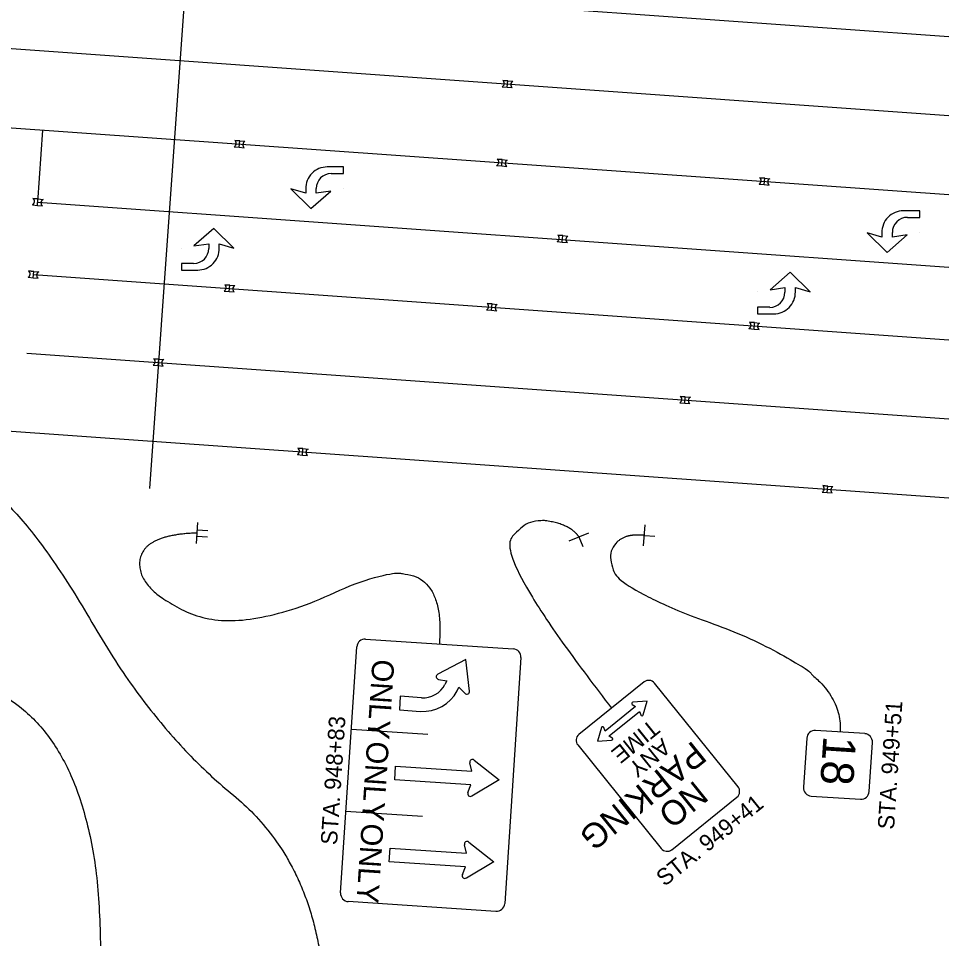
# Model space of a CAD drawing. Extents: x 1847379 to 1850904, y 217032 to 220169.
# Drawn here: x 1848989.3 to 1849129.7, y 218737.1 to 218877.1 of the extents above; entities that cross this region are included whole.
import ezdxf

# ---------------------------------------------------------------- set-up
doc = ezdxf.new("R2010")
doc.units = 0
for name, color, linetype in [('BR_P_Gen_Phase_Construction', 7, 'Continuous'), ('PM_P_Cells', 7, 'Continuous'), ('PM_P_Channelizing_Line', 7, 'Continuous'), ('PM_P_CL_Double_Solid', 7, 'Continuous'), ('PM_P_Edge_Line', 7, 'Continuous'), ('PM_P_Lane_Line', 7, 'Continuous'), ('PM_P_Stop_Line', 7, 'Continuous'), ('PM_X_Cells', 7, 'Continuous'), ('SN_X_Public', 7, 'Continuous')]:
    doc.layers.add(name, color=color, linetype=linetype)

msp = doc.modelspace()

# ---------------------------------------------------------------- linework, layer by layer
at = {"layer": 'BR_P_Gen_Phase_Construction'}
msp.add_line((1849015.28, 218890.32), (1849009.23, 218805.57), dxfattribs=at)
at = {"layer": 'PM_P_Cells'}
for p, q in [((1849062.86, 218866.66), (1849063.63, 218866.6)), ((1849062.86, 218866.66), (1849063.63, 218866.6)), ((1849063.72, 218867.57), (1849062.95, 218867.64)), ((1849062.95, 218867.64), (1849063.72, 218867.57)), ((1849063.63, 218866.6), (1849063.72, 218867.57)), ((1849063.63, 218866.6), (1849064.4, 218866.53)), ((1849063.72, 218867.57), (1849064.49, 218867.5)), ((1849022.98, 218858.44), (1849022.22, 218858.51)), ((1849022.22, 218858.51), (1849022.98, 218858.44)), ((1849022.9, 218857.47), (1849022.98, 218858.44)), ((1849022.98, 218858.44), (1849023.75, 218858.38)), ((1849022.13, 218857.54), (1849022.9, 218857.47)), ((1849022.13, 218857.54), (1849022.9, 218857.47)), ((1849022.9, 218857.47), (1849023.66, 218857.4)), ((1849062.88, 218855.6), (1849062.12, 218855.67)), ((1849062.12, 218855.67), (1849062.88, 218855.6)), ((1849062.8, 218854.62), (1849062.88, 218855.6)), ((1849062.88, 218855.6), (1849063.65, 218855.53)), ((1849038.76, 218854.48), (1849036.28, 218854.48)), ((1849038.76, 218853.48), (1849038.76, 218854.48)), ((1849062.03, 218854.69), (1849062.8, 218854.62)), ((1849062.03, 218854.69), (1849062.8, 218854.62)), ((1849062.8, 218854.62), (1849063.56, 218854.56)), ((1849036.89, 218853.48), (1849038.76, 218853.48)), ((1849102.78, 218852.75), (1849102.01, 218852.82)), ((1849102.01, 218852.82), (1849102.78, 218852.75)), ((1849102.69, 218851.78), (1849102.78, 218852.75)), ((1849102.78, 218852.75), (1849103.55, 218852.68)), ((1849030.76, 218851.15), (1849030.76, 218851.15)), ((1849033, 218850.48), (1849030.76, 218851.15)), ((1849030.76, 218851.15), (1849033.8, 218848.15)), ((1849033, 218851.15), (1849033, 218850.48)), ((1849034.6, 218850.48), (1849034.6, 218851.18)), ((1849038.76, 218851.15), (1849038.76, 218851.15)), ((1849101.93, 218851.85), (1849102.69, 218851.78)), ((1849101.93, 218851.85), (1849102.69, 218851.78)), ((1849102.69, 218851.78), (1849103.46, 218851.71)), ((1848992.29, 218849.61), (1848991.53, 218849.68)), ((1848991.53, 218849.68), (1848992.29, 218849.61)), ((1849033.8, 218848.15), (1849036.84, 218850.81)), ((1849036.84, 218850.81), (1849034.6, 218850.48)), ((1848991.44, 218848.7), (1848992.21, 218848.63)), ((1848991.44, 218848.7), (1848992.21, 218848.63)), ((1848992.21, 218848.63), (1848992.29, 218849.61)), ((1848992.21, 218848.63), (1848992.97, 218848.57)), ((1848992.29, 218849.61), (1848993.06, 218849.54)), ((1849126.35, 218847.81), (1849123.87, 218847.81)), ((1849126.35, 218846.81), (1849126.35, 218847.81)), ((1849124.49, 218846.81), (1849126.35, 218846.81)), ((1849019.05, 218845.13), (1849016.01, 218842.46)), ((1849022.09, 218842.13), (1849019.05, 218845.13)), ((1849072.1, 218844.03), (1849071.33, 218844.1)), ((1849071.33, 218844.1), (1849072.1, 218844.03)), ((1849118.35, 218844.48), (1849118.35, 218844.48)), ((1849120.59, 218843.81), (1849118.35, 218844.48)), ((1849118.35, 218844.48), (1849121.39, 218841.48)), ((1849120.59, 218844.48), (1849120.59, 218843.81)), ((1849121.39, 218841.48), (1849124.43, 218844.14)), ((1849122.19, 218843.81), (1849122.19, 218844.51)), ((1849124.43, 218844.14), (1849122.19, 218843.81)), ((1849126.35, 218844.48), (1849126.35, 218844.48)), ((1849016.01, 218842.46), (1849018.25, 218842.79)), ((1849018.25, 218842.79), (1849018.25, 218842.09)), ((1849019.85, 218842.13), (1849019.85, 218842.79)), ((1849019.85, 218842.79), (1849022.09, 218842.13)), ((1849071.24, 218843.12), (1849072.01, 218843.05)), ((1849071.24, 218843.12), (1849072.01, 218843.05)), ((1849072.01, 218843.05), (1849072.1, 218844.03)), ((1849072.01, 218843.05), (1849072.78, 218842.99)), ((1849072.1, 218844.03), (1849072.87, 218843.96)), ((1849014.09, 218842.13), (1849014.09, 218842.13)), ((1849022.09, 218842.13), (1849022.09, 218842.13)), ((1848991.64, 218838.6), (1848990.87, 218838.67)), ((1848990.87, 218838.67), (1848991.64, 218838.6)), ((1848991.55, 218837.63), (1848991.64, 218838.6)), ((1848991.64, 218838.6), (1848992.4, 218838.53)), ((1849015.96, 218839.79), (1849014.09, 218839.79)), ((1849014.09, 218839.79), (1849014.09, 218838.79)), ((1849014.09, 218838.79), (1849016.57, 218838.79)), ((1849106.65, 218838.46), (1849103.61, 218835.79)), ((1849109.69, 218835.46), (1849106.65, 218838.46)), ((1848990.78, 218837.7), (1848991.55, 218837.63)), ((1848990.78, 218837.7), (1848991.55, 218837.63)), ((1848991.55, 218837.63), (1848992.32, 218837.56)), ((1849021.45, 218836.5), (1849020.68, 218836.57)), ((1849020.68, 218836.57), (1849021.45, 218836.5)), ((1849021.36, 218835.53), (1849021.45, 218836.5)), ((1849021.45, 218836.5), (1849022.22, 218836.43)), ((1849103.61, 218835.79), (1849105.85, 218836.13)), ((1849105.85, 218836.13), (1849105.85, 218835.42)), ((1849107.45, 218835.46), (1849107.45, 218836.13)), ((1849107.45, 218836.13), (1849109.69, 218835.46)), ((1849020.59, 218835.6), (1849021.36, 218835.53)), ((1849020.59, 218835.6), (1849021.36, 218835.53)), ((1849021.36, 218835.53), (1849022.13, 218835.46)), ((1849101.69, 218835.46), (1849101.69, 218835.46)), ((1849109.69, 218835.46), (1849109.69, 218835.46)), ((1849061.35, 218833.65), (1849060.58, 218833.72)), ((1849060.58, 218833.72), (1849061.35, 218833.65)), ((1849061.26, 218832.68), (1849061.35, 218833.65)), ((1849061.35, 218833.65), (1849062.12, 218833.58)), ((1849103.55, 218833.13), (1849101.69, 218833.13)), ((1849101.69, 218833.13), (1849101.69, 218832.13)), ((1849060.49, 218832.75), (1849061.26, 218832.68)), ((1849060.49, 218832.75), (1849061.26, 218832.68)), ((1849061.26, 218832.68), (1849062.03, 218832.61)), ((1849101.69, 218832.13), (1849104.17, 218832.13)), ((1849101.25, 218830.8), (1849100.48, 218830.87)), ((1849100.48, 218830.87), (1849101.25, 218830.8)), ((1849101.16, 218829.83), (1849101.25, 218830.8)), ((1849101.25, 218830.8), (1849102.01, 218830.73)), ((1849100.39, 218829.9), (1849101.16, 218829.83)), ((1849100.39, 218829.9), (1849101.16, 218829.83)), ((1849101.16, 218829.83), (1849101.93, 218829.76)), ((1849010.65, 218825.24), (1849009.88, 218825.31)), ((1849009.88, 218825.31), (1849010.65, 218825.24)), ((1849010.56, 218824.27), (1849010.65, 218825.24)), ((1849010.65, 218825.24), (1849011.41, 218825.17)), ((1849009.79, 218824.34), (1849010.56, 218824.27)), ((1849009.79, 218824.34), (1849010.56, 218824.27)), ((1849010.56, 218824.27), (1849011.33, 218824.2)), ((1849090.71, 218819.52), (1849089.95, 218819.59)), ((1849089.95, 218819.59), (1849090.71, 218819.52)), ((1849090.63, 218818.55), (1849090.71, 218819.52)), ((1849090.71, 218819.52), (1849091.48, 218819.46)), ((1849089.86, 218818.62), (1849090.63, 218818.55)), ((1849089.86, 218818.62), (1849090.63, 218818.55)), ((1849090.63, 218818.55), (1849091.39, 218818.48)), ((1849031.73, 218810.74), (1849032.5, 218810.67)), ((1849031.73, 218810.74), (1849032.5, 218810.67)), ((1849032.58, 218811.64), (1849031.82, 218811.71)), ((1849031.82, 218811.71), (1849032.58, 218811.64)), ((1849032.5, 218810.67), (1849032.58, 218811.64)), ((1849032.5, 218810.67), (1849033.26, 218810.6)), ((1849032.58, 218811.64), (1849033.35, 218811.57)), ((1849111.52, 218805.04), (1849112.29, 218804.97)), ((1849111.52, 218805.04), (1849112.29, 218804.97)), ((1849112.38, 218805.95), (1849111.61, 218806.02)), ((1849111.61, 218806.02), (1849112.38, 218805.95)), ((1849112.29, 218804.97), (1849112.38, 218805.95)), ((1849112.29, 218804.97), (1849113.06, 218804.91)), ((1849112.38, 218805.95), (1849113.15, 218805.88))]:
    msp.add_line(p, q, dxfattribs=at)
for centre, radius, start, end in [((1849062.61, 218867.18), 0.576, 296.8063, 52.8586), ((1849062.61, 218867.18), 0.576, 296.8063, 52.8586), ((1849064.75, 218866.98), 0.576, 116.8063, 232.8586), ((1849021.87, 218858.06), 0.576, 296.8063, 52.8586), ((1849021.87, 218858.06), 0.576, 296.8063, 52.8586), ((1849024.01, 218857.86), 0.576, 116.8063, 232.8586), ((1849061.77, 218855.21), 0.576, 296.8063, 52.8586), ((1849061.77, 218855.21), 0.576, 296.8063, 52.8586), ((1849063.91, 218855.01), 0.576, 116.8063, 232.8586), ((1849036.28, 218851.2), 3.28, 90, 180.9085), ((1849036.89, 218851.18), 2.3, 90, 180), ((1849101.67, 218852.36), 0.576, 296.8063, 52.8586), ((1849101.67, 218852.36), 0.576, 296.8063, 52.8586), ((1849103.81, 218852.17), 0.576, 116.8063, 232.8586), ((1848991.18, 218849.22), 0.576, 296.8063, 52.8586), ((1848991.18, 218849.22), 0.576, 296.8063, 52.8586), ((1848993.32, 218849.02), 0.576, 116.8063, 232.8586), ((1849123.87, 218844.53), 3.28, 90, 180.9085), ((1849124.49, 218844.51), 2.3, 90, 180), ((1849070.98, 218843.64), 0.576, 296.8063, 52.8586), ((1849070.98, 218843.64), 0.576, 296.8063, 52.8586), ((1849073.13, 218843.44), 0.576, 116.8063, 232.8586), ((1849015.96, 218842.09), 2.3, 270, 360), ((1849016.57, 218842.08), 3.28, 270, 0.9085), ((1848990.52, 218838.21), 0.576, 296.8063, 52.8586), ((1848990.52, 218838.21), 0.576, 296.8063, 52.8586), ((1848992.66, 218838.02), 0.576, 116.8063, 232.8586), ((1849020.33, 218836.11), 0.576, 296.8063, 52.8586), ((1849020.33, 218836.11), 0.576, 296.8063, 52.8586), ((1849022.48, 218835.92), 0.576, 116.8063, 232.8586), ((1849103.55, 218835.42), 2.3, 270, 360), ((1849104.17, 218835.41), 3.28, 270, 0.9085), ((1849060.23, 218833.26), 0.576, 296.8063, 52.8586), ((1849060.23, 218833.26), 0.576, 296.8063, 52.8586), ((1849062.38, 218833.07), 0.576, 116.8063, 232.8586), ((1849100.13, 218830.41), 0.576, 296.8063, 52.8586), ((1849100.13, 218830.41), 0.576, 296.8063, 52.8586), ((1849102.27, 218830.22), 0.576, 116.8063, 232.8586), ((1849009.53, 218824.85), 0.576, 296.8063, 52.8586), ((1849009.53, 218824.85), 0.576, 296.8063, 52.8586), ((1849011.67, 218824.66), 0.576, 116.8063, 232.8586), ((1849089.6, 218819.13), 0.576, 296.8063, 52.8586), ((1849089.6, 218819.13), 0.576, 296.8063, 52.8586), ((1849091.74, 218818.94), 0.576, 116.8063, 232.8586), ((1849031.47, 218811.25), 0.576, 296.8063, 52.8586), ((1849031.47, 218811.25), 0.576, 296.8063, 52.8586), ((1849033.61, 218811.06), 0.576, 116.8063, 232.8586), ((1849111.27, 218805.56), 0.576, 296.8063, 52.8586), ((1849111.27, 218805.56), 0.576, 296.8063, 52.8586), ((1849113.41, 218805.36), 0.576, 116.8063, 232.8586)]:
    msp.add_arc(centre, radius, start, end, dxfattribs=at)
at = {"layer": 'PM_P_Channelizing_Line'}
for p, q in [((1848983.04, 218860.81), (1849486.82, 218824.85)), ((1848991.59, 218838.14), (1849494.91, 218802.22))]:
    msp.add_line(p, q, dxfattribs=at)
at = {"layer": 'PM_P_CL_Double_Solid'}
msp.add_line((1848992.25, 218849.12), (1849486.03, 218813.88), dxfattribs=at)
at = {"layer": 'PM_P_Edge_Line'}
for p, q in [((1848960.09, 218886.51), (1849497.6, 218848.14)), ((1848953.55, 218816.79), (1849519.44, 218776.41))]:
    msp.add_line(p, q, dxfattribs=at)
at = {"layer": 'PM_P_Lane_Line'}
for p, q in [((1848983.9, 218872.78), (1849487.67, 218836.82)), ((1848990.62, 218826.18), (1849494.05, 218790.25))]:
    msp.add_line(p, q, dxfattribs=at)
at = {"layer": 'PM_P_Stop_Line'}
msp.add_line((1848992.25, 218849.12), (1848993.02, 218860.09), dxfattribs=at)
at = {"layer": 'PM_X_Cells'}
for p, q in [((1849019.05, 218845.13), (1849016.01, 218842.46)), ((1849022.09, 218842.13), (1849019.05, 218845.13)), ((1849016.01, 218842.46), (1849018.25, 218842.79)), ((1849018.25, 218842.79), (1849018.25, 218842.09)), ((1849019.85, 218842.13), (1849019.85, 218842.79)), ((1849019.85, 218842.79), (1849022.09, 218842.13)), ((1849014.09, 218842.13), (1849014.09, 218842.13)), ((1849022.09, 218842.13), (1849022.09, 218842.13)), ((1849015.96, 218839.79), (1849014.09, 218839.79)), ((1849014.09, 218839.79), (1849014.09, 218838.79)), ((1849014.09, 218838.79), (1849016.57, 218838.79)), ((1849106.65, 218838.46), (1849103.61, 218835.79)), ((1849109.69, 218835.46), (1849106.65, 218838.46)), ((1849103.61, 218835.79), (1849105.85, 218836.13)), ((1849105.85, 218836.13), (1849105.85, 218835.42)), ((1849107.45, 218835.46), (1849107.45, 218836.13)), ((1849107.45, 218836.13), (1849109.69, 218835.46)), ((1849101.69, 218835.46), (1849101.69, 218835.46)), ((1849109.69, 218835.46), (1849109.69, 218835.46)), ((1849103.55, 218833.13), (1849101.69, 218833.13)), ((1849101.69, 218833.13), (1849101.69, 218832.13)), ((1849101.69, 218832.13), (1849104.17, 218832.13))]:
    msp.add_line(p, q, dxfattribs=at)
for centre, radius, end in [((1849015.96, 218842.09), 2.3, 0), ((1849016.57, 218842.08), 3.28, 0.9085), ((1849103.55, 218835.42), 2.3, 0), ((1849104.17, 218835.41), 3.28, 0.9085)]:
    msp.add_arc(centre, radius, 270, end, dxfattribs=at)
at = {"layer": 'SN_X_Public'}
for p, q in [((1849016.39, 218797.22), (1849016.58, 218800.41)), ((1849016.51, 218799.29), (1849018.11, 218799.2)), ((1849084.38, 218796.85), (1849084.62, 218800.04)), ((1849016.46, 218798.33), (1849018.05, 218798.24)), ((1849016.48, 218798.81), (1849016.48, 218798.81)), ((1849073.05, 218797.64), (1849076.02, 218798.84)), ((1849074.53, 218798.24), (1849075.13, 218796.75)), ((1849084.5, 218798.44), (1849086.09, 218798.32)), ((1849057.35, 218779.58), (1849053.07, 218777.33)), ((1849057.92, 218774.78), (1849057.35, 218779.58)), ((1849053.19, 218776.55), (1849054.45, 218776.32)), ((1849054.45, 218776.32), (1849054.16, 218775.76)), ((1849056, 218774.79), (1849056.3, 218775.35)), ((1849056.3, 218775.35), (1849057.21, 218774.44)), ((1849047.37, 218773.98), (1849047.24, 218771.9)), ((1849050.59, 218773.76), (1849047.37, 218773.98)), ((1849082.65, 218772.75), (1849083.15, 218772.42)), ((1849084.89, 218773.23), (1849082.74, 218773.09)), ((1849084.3, 218771.15), (1849084.89, 218773.23)), ((1849047.24, 218771.9), (1849050.46, 218771.69)), ((1849079.11, 218767.96), (1849083.73, 218771.69)), ((1849083.73, 218771.69), (1849083.73, 218771.69)), ((1849083.73, 218771.69), (1849083.95, 218771.14)), ((1849080.93, 218770.42), (1849080.93, 218770.42)), ((1849051.58, 218768.17), (1849039.94, 218768.93)), ((1849077.95, 218769.23), (1849077.35, 218767.15)), ((1849078.51, 218768.69), (1849078.3, 218769.25)), ((1849077.35, 218767.15), (1849079.51, 218767.29)), ((1849079.6, 218767.63), (1849079.1, 218767.96)), ((1849079.1, 218767.96), (1849079.11, 218767.96)), ((1849058.61, 218764.29), (1849062.4, 218761.29)), ((1849046.54, 218761.3), (1849046.67, 218763.37)), ((1849046.67, 218763.37), (1849058.25, 218762.61)), ((1849058.25, 218762.61), (1849057.95, 218763.86)), ((1849058.11, 218760.53), (1849046.54, 218761.3)), ((1849062.4, 218761.29), (1849058.25, 218758.82)), ((1849057.65, 218759.33), (1849058.11, 218760.53)), ((1849050.76, 218755.69), (1849039.12, 218756.46)), ((1849057.79, 218751.82), (1849061.58, 218748.82)), ((1849045.71, 218748.82), (1849045.85, 218750.9)), ((1849045.85, 218750.9), (1849057.43, 218750.14)), ((1849057.43, 218750.14), (1849057.12, 218751.39)), ((1849057.29, 218748.06), (1849045.71, 218748.82)), ((1849061.58, 218748.82), (1849057.43, 218746.35)), ((1849056.82, 218746.86), (1849057.29, 218748.06))]:
    msp.add_line(p, q, dxfattribs=at)
for points in [[(1849042.1, 218782.68), (1849064.55, 218781.2)], [(1849038.3, 218744.09), (1849040.77, 218781.51)], [(1849065.72, 218779.87), (1849063.25, 218742.45)], [(1849084.44, 218776.17), (1849074.52, 218768.17)], [(1849098.73, 218760.23), (1849086.03, 218776)], [(1849083.15, 218772.42), (1849078.52, 218768.69)], [(1849118, 218768.3), (1849110.51, 218768.79)], [(1849109.18, 218767.62), (1849108.69, 218760.14)], [(1849118.67, 218759.48), (1849119.16, 218766.97)], [(1849074.35, 218766.59), (1849087.05, 218750.82)], [(1849088.64, 218750.65), (1849098.56, 218758.65)], [(1849109.86, 218758.81), (1849117.34, 218758.32)], [(1849061.92, 218741.28), (1849039.47, 218742.76)]]:
    msp.add_lwpolyline(points, dxfattribs=at)
for centre, radius, start, end in [((1849042.02, 218781.43), 1.25, 86.2275, 176.2275), ((1849064.47, 218779.95), 1.25, 356.2275, 86.2275), ((1849053.26, 218776.96), 0.417, 117.7547, 259.6328), ((1849050.84, 218777.51), 3.75, 266.2275, 332.3289), ((1849085.15, 218775.29), 1.12, 38.8676, 128.8676), ((1849050.84, 218777.51), 5.83, 266.2275, 332.3174), ((1849057.5, 218774.73), 0.417, 224.9091, 6.7872), ((1849082.75, 218772.91), 0.182, 93.7884, 236.5054), ((1849084.12, 218771.2), 0.182, 201.2298, 343.9469), ((1849078.13, 218769.18), 0.182, 21.2298, 163.9469), ((1849110.43, 218767.54), 1.25, 86.2508, 176.2508), ((1849117.91, 218767.05), 1.25, 356.2508, 86.2508), ((1849075.22, 218767.29), 1.12, 128.8676, 218.8676), ((1849079.5, 218767.48), 0.182, 273.7884, 56.5054), ((1849058.35, 218763.96), 0.417, 51.7113, 193.5894), ((1849097.86, 218759.53), 1.12, 308.8676, 38.8676), ((1849109.94, 218760.06), 1.25, 176.2508, 266.2508), ((1849058.04, 218759.18), 0.417, 158.8657, 300.7438), ((1849117.42, 218759.57), 1.25, 266.2508, 356.2508), ((1849057.53, 218751.49), 0.417, 51.7113, 193.5894), ((1849087.93, 218751.53), 1.12, 218.8676, 308.8676), ((1849057.21, 218746.71), 0.417, 158.8657, 300.7438), ((1849039.55, 218744.01), 1.25, 176.2275, 266.2275), ((1849062, 218742.53), 1.25, 266.2275, 356.2275)]:
    msp.add_arc(centre, radius, start, end, dxfattribs=at)
for points in [[(1848968.65, 218812.08), (1848963.26, 218811.77), (1848959.87, 218808.8), (1848962.37, 218795.34), (1848972.61, 218782.93), (1849002.07, 218764.9), (1849001.83, 218733.74)], [(1848970.64, 218811.94), (1848978.12, 218810.73), (1848991.68, 218800.45), (1849010.03, 218768.73), (1849033.87, 218749.22), (1849035.6, 218731.52)], [(1849074.53, 218798.24), (1849073.27, 218800.07), (1849066.4, 218801.17), (1849062.09, 218794.66), (1849079.48, 218772.17)], [(1849016.48, 218798.81), (1849007.92, 218798.54), (1849007.56, 218790.03), (1849023.39, 218783.16), (1849054.48, 218797.6), (1849053.33, 218781.94)], [(1849084.5, 218798.44), (1849081.43, 218798.8), (1849078.71, 218795.51), (1849081.17, 218790.01), (1849114.91, 218777.46), (1849114.25, 218768.54)]]:
    msp.add_open_spline(points, degree=2, dxfattribs=at)

# ---------------------------------------------------------------- texts
for s, height, rotation, p in [('ONLY', 3.333, 266.2275, (1849043.16, 218779.68)), ('STA. 949+51', 2.5, 86.2508, (1849122.45, 218753.67)), ('STA. 948+83', 2.5, 86.2275, (1849037.76, 218751.32)), ('TIME', 2.5, 218.8676, (1849085.48, 218770.58)), ('ONLY', 3.333, 266.2275, (1849042.33, 218767.21)), ('PARKING', 3.75, 218.8676, (1849091.9, 218767.33)), ('ANY', 2.5, 218.8676, (1849087.19, 218767.74)), ('18', 5, 266.2508, (1849111.72, 218768.04)), ('NO', 3.75, 218.8676, (1849092.15, 218761.31)), ('STA. 949+41', 2.5, 38.8676, (1849087.56, 218744.97)), ('ONLY', 3.333, 266.2275, (1849041.51, 218754.74))]:
    msp.add_text(s, height=height, rotation=rotation, dxfattribs=at).set_placement(p)

doc.saveas('drawing.dxf')
